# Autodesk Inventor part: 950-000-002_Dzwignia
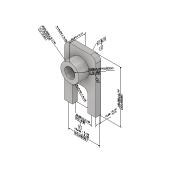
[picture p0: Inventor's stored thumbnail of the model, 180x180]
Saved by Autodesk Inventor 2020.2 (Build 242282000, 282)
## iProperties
Created: 2018-01
Part Number: 950-000-002_Dzwignia
Material: Aluminium 6061
Document SubType Name: Modeling
Designer: F.Stasiak
Density: 2.7 g/cm^3
Appearance: Aluminium — polerowane
Manager: www.cadconsulting.pl
Company: Fabian Stasiak CAD Consulting
Author: F.Stasiak
Subject: Zbiór ćwiczeń. Autodesk Inventor 2020. Kurs podstawowy
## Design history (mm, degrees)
sketch "Szkic1"
  geometry: L1 (-30, 50)-(30, 50); L2 (30, 50)-(30, -50); L3 (30, -50)-(-30, -50); L4 (-30, -50)-(-30, 50); L5 (-30, 50)-(30, -50); L6 (30, 50)-(-30, -50); 1 further point
  constraints: 12 end point, 2 midpoint, 2 parallel, 1 horizontal, 1 perpendicular
  dimensions: "d0" = 60 distance of L2.end L3.end; "d1" = 100 distance of L1.end L2.end
extrude "Wyciągnięcie proste1" new body sketch "Szkic1" distance "d2" = 10; taper "d3" = 0 deg
sketch "Szkic2"
  geometry: L1 (-30, -50)-(30, -50) reference; C1 r 17.5 at (0, 20); 1 further point
  constraints: 1 centre point, 1 vertical alignment
  dimensions: "d4" = 35 diameter of C1; "d5" = 70 distance from line of L1 C1.centre
extrude "Wyciągnięcie proste2" join sketch "Szkic2" distance "d6" = 20; taper "d7" = 0 deg
hole "Otwór1" diameter "d10" = 20; stored, may be unused: countersink angle "d14" = 90 deg, drill point angle "d16" = 118 deg; dims "d8" = 10, "d9" = 10, "d11" = 6, "d12" = 4, "d13" = 2, "d15" = 8
sketch "Szkic3"
  geometry: L1 (-30, -50)-(30, -50) reference; L2 (-15, -50)-(15, -50); L3 (15, -50)-(15, -10); L4 (15, -10)-(-15, -10); L5 (-15, -10)-(-15, -50); 2 further points
  constraints: 8 end point, 2 equal length, 2 midpoint, 1 horizontal, 1 perpendicular
  dimensions: "d17" = 30 distance of L4.end L3.end; "d18" = 40 distance of L3.end L2.end
extrude "Wyciągnięcie proste3" cut sketch "Szkic3" extent not by distance; stored distance "d19" = 20; taper "d20" = 0 deg
fillet "Zaokrąglenie1" dims "d21" = 10
node "Bryła1"
node "Opisy"
node "Elementy tolerancji"
node "Powierzchnia płaska 1" dims "d22" = 6.42906 (derived), "d23" = 8.73973 (derived), "d24" = 0.15 (derived), "d25" = 0 (derived), "d26" = 0 (derived), "d27" = 4.9721 (derived), "d28" = 0 (derived), "d29" = 0 (derived), "d31" = 2 (derived), "d32" = 0 (derived), "d33" = 0 (derived), "d41" = 7.66583 (derived), "d42" = 6.59869 (derived), "d43" = 30 (derived), "d44" = 2 (derived), "d45" = 0 (derived), "d46" = 0 (derived), "d47" = 6.24466 (derived), "d48" = 6.95816 (derived), "d49" = 2.80585 (derived), "d50" = 35 (derived), "d51" = 0.025 (derived), "d52" = 0 (derived), "d53" = 0 (derived)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
node "Tolerancja kształtu i położenia 1"
node "Identyfikator odniesienia cząstkowego 1" dims "d0" = 60, "d22" = 6.42906 (derived), "d23" = 8.73973 (derived), "d24" = 0.15 (derived), "d25" = 0 (derived), "d26" = 0 (derived), "d27" = 4.9721 (derived), "d28" = 0 (derived), "d29" = 0 (derived), "d31" = 2 (derived), "d32" = 0 (derived), "d33" = 0 (derived), "d41" = 7.66583 (derived), "d42" = 6.59869 (derived), "d43" = 30 (derived), "d44" = 2 (derived), "d45" = 0 (derived), "d46" = 0 (derived), "d47" = 6.24466 (derived), "d48" = 6.95816 (derived), "d49" = 2.80585 (derived), "d50" = 35 (derived), "d51" = 0.025 (derived), "d52" = 0 (derived)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
node "Układ odniesienia 1"
node "Otwór prosty 1" dims "d22" = 6.42906 (derived), "d23" = 8.73973 (derived), "d24" = 0.15 (derived), "d25" = 0 (derived), "d26" = 0 (derived), "d27" = 4.9721 (derived), "d28" = 0 (derived), "d29" = 0 (derived), "d31" = 2 (derived), "d32" = 0 (derived), "d33" = 0 (derived), "d41" = 7.66583 (derived), "d42" = 6.59869 (derived), "d43" = 30 (derived), "d44" = 2 (derived), "d45" = 0 (derived), "d46" = 0 (derived), "d47" = 6.24466 (derived), "d48" = 6.95816 (derived), "d49" = 2.80585 (derived), "d50" = 35 (derived), "d51" = 0.025 (derived), "d52" = 0 (derived), "d53" = 0 (derived)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
node "Opis otworu 1" dims "d0" = 60, "d17" = 30, "d18" = 40
node "Tolerancja kształtu i położenia 2"
node "Identyfikator odniesienia cząstkowego 2" dims "d0" = 60, "d22" = 6.42906 (derived), "d23" = 8.73973 (derived), "d24" = 0.15 (derived), "d25" = 0 (derived), "d26" = 0 (derived), "d27" = 4.9721 (derived), "d28" = 0 (derived), "d29" = 0 (derived), "d31" = 2 (derived), "d32" = 0 (derived), "d33" = 0 (derived), "d41" = 7.66583 (derived), "d42" = 6.59869 (derived), "d43" = 30 (derived), "d44" = 2 (derived), "d45" = 0 (derived), "d46" = 0 (derived), "d47" = 6.24466 (derived), "d48" = 6.95816 (derived), "d49" = 2.80585 (derived), "d50" = 35 (derived), "d51" = 0.025 (derived), "d52" = 0 (derived)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
node "Układ odniesienia 3"
node "Wał 1"
node "Powierzchnia płaska 2"
node "Powierzchnia płaska 3"
node "Szczelina 1" dims "d22" = 6.42906 (derived), "d23" = 8.73973 (derived), "d24" = 0.15 (derived), "d25" = 0 (derived), "d26" = 0 (derived), "d27" = 4.9721 (derived), "d28" = 0 (derived), "d29" = 0 (derived), "d31" = 2 (derived), "d32" = 0 (derived), "d33" = 0 (derived), "d41" = 7.66583 (derived), "d42" = 6.59869 (derived), "d43" = 30 (derived), "d44" = 2 (derived), "d45" = 0 (derived), "d46" = 0 (derived), "d47" = 6.24466 (derived), "d48" = 6.95816 (derived), "d49" = 2.80585 (derived), "d50" = 35 (derived), "d51" = 0.025 (derived), "d52" = 0 (derived), "d53" = 0 (derived)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
node "Wymiar liniowy 1" dims "d0" = 60, "d17" = 30, "d18" = 40, "d43" = 30 (derived)
node "Tolerancja kształtu i położenia 4"
node "Identyfikator odniesienia cząstkowego 3" dims "d0" = 60, "d22" = 6.42906 (derived), "d23" = 8.73973 (derived), "d24" = 0.15 (derived), "d25" = 0 (derived), "d26" = 0 (derived), "d27" = 4.9721 (derived), "d28" = 0 (derived), "d29" = 0 (derived), "d31" = 2 (derived), "d32" = 0 (derived), "d33" = 0 (derived), "d41" = 7.66583 (derived), "d42" = 6.59869 (derived), "d43" = 30 (derived), "d44" = 2 (derived), "d45" = 0 (derived), "d46" = 0 (derived), "d47" = 6.24466 (derived), "d48" = 6.95816 (derived), "d49" = 2.80585 (derived), "d50" = 35 (derived), "d51" = 0.025 (derived), "d52" = 0 (derived)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
node "Układ odniesienia 4"
node "Wymiar średnicy 1" dims "d0" = 60, "d17" = 30, "d18" = 40, "d50" = 35 (derived)
node "Tolerancja kształtu i położenia 5"
node "Powierzchnia płaska 4"
node "Powierzchnia płaska 5"
node "Płyta 1"
node "Wymiar liniowy 2" dims "d0" = 60, "d17" = 30, "d18" = 40, "d59" = 100 (derived)
node "Tolerancja kształtu i położenia 6"
node "Uwaga ogólna 1"
node "Ogólna tolerancja profilu powierzchni"
node "Wymiar liniowy 3" dims "d0" = 60, "d17" = 30, "d18" = 40, "d66" = 10 (derived)
node "Wymiar promienia 1" dims "d0" = 60, "d17" = 30, "d18" = 40, "d68" = 10 (derived)
node "Wymiar promienia 2" dims "d0" = 60, "d17" = 30, "d18" = 40, "d70" = 10 (derived)
node "Powierzchnia płaska 6"
node "Powierzchnia płaska 7"
node "Płyta 2"
node "Wymiar liniowy 4" dims "d0" = 60, "d17" = 30, "d18" = 40, "d73" = 60 (derived)
node "Tolerancja kształtu i położenia 8"
node "Wymiar liniowy 5" dims "d0" = 60, "d17" = 30, "d18" = 40, "d77" = 30 (derived)
